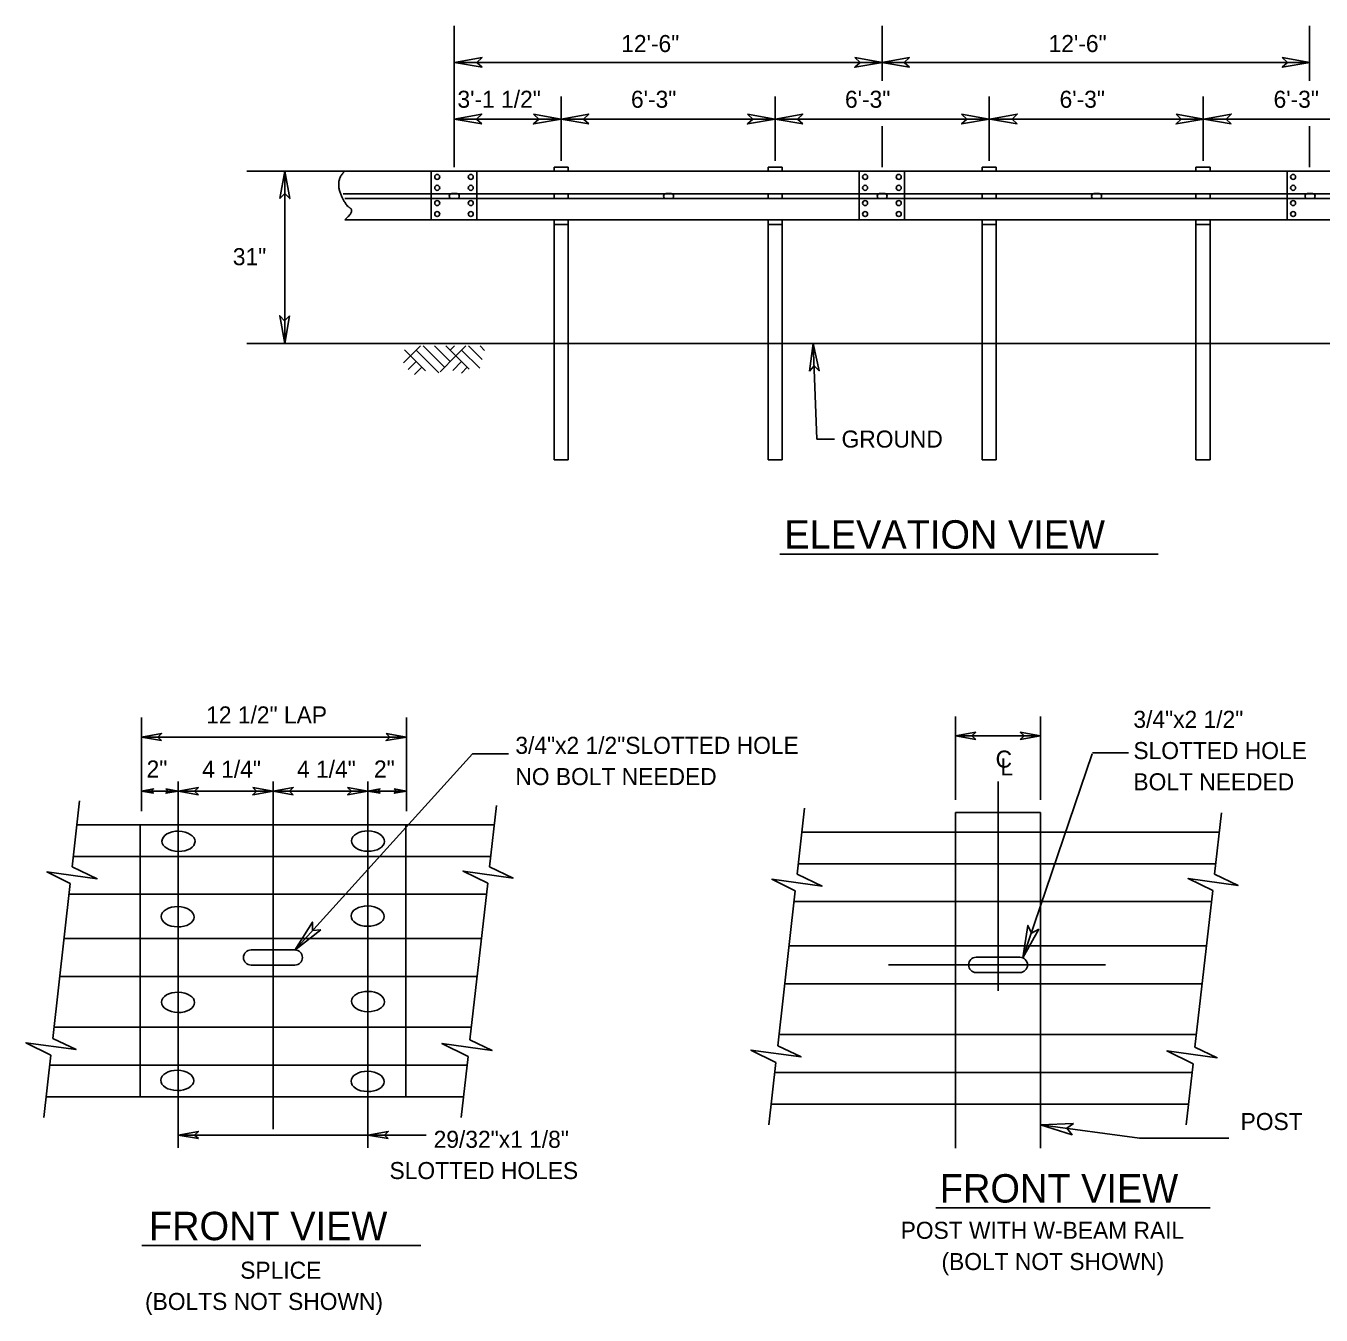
# Model space of a CAD drawing. Extents: x 12.4 to 19.6, y 6 to 16.1.
# Drawn here: x 12.43 to 16.991, y 11.52 to 16.059 of the extents above; entities that cross this region are included whole.
import ezdxf

# ---------------------------------------------------------------- set-up
doc = ezdxf.new("R2010")
doc.units = 0
for name, color, linetype in [('DETL-DIMS', 7, 'Continuous'), ('DETL-LINE', 7, 'Continuous'), ('DETL-NOTE', 7, 'Continuous'), ('DETL-PATT', 7, 'Continuous'), ('DETL-TITL', 7, 'Continuous')]:
    doc.layers.add(name, color=color, linetype=linetype)

msp = doc.modelspace()

# ---------------------------------------------------------------- linework, layer by layer
at = {"layer": 'DETL-DIMS'}
for p, q in [((13.9381, 15.5612), (13.9381, 16.0592)), ((15.4453, 15.8654), (15.4453, 16.0592)), ((16.9503, 15.8654), (16.9503, 16.0592)), ((13.9389, 15.9307), (14.0362, 15.9479)), ((15.4461, 15.9307), (13.9389, 15.9307)), ((13.9389, 15.9307), (14.0362, 15.9136)), ((14.0178, 15.9307), (14.0362, 15.9479)), ((14.0362, 15.9136), (14.0178, 15.9307)), ((15.4461, 15.9307), (15.3489, 15.9479)), ((15.3489, 15.9479), (15.3673, 15.9307)), ((15.4461, 15.9307), (15.3489, 15.9136)), ((15.3673, 15.9307), (15.3489, 15.9136)), ((15.444, 15.9307), (15.5412, 15.9479)), ((15.444, 15.9307), (15.5412, 15.9136)), ((16.9512, 15.9307), (15.444, 15.9307)), ((15.5229, 15.9307), (15.5412, 15.9479)), ((15.5412, 15.9136), (15.5229, 15.9307)), ((16.9512, 15.9307), (16.854, 15.9479)), ((16.854, 15.9479), (16.8723, 15.9307)), ((16.9512, 15.9307), (16.854, 15.9136)), ((16.8723, 15.9307), (16.854, 15.9136)), ((14.3149, 15.5844), (14.3149, 15.8102)), ((15.0685, 15.5844), (15.0685, 15.8102)), ((15.822, 15.5844), (15.822, 15.8102)), ((16.5756, 15.5844), (16.5756, 15.8102)), ((13.9377, 15.7313), (14.035, 15.7484)), ((14.0166, 15.7313), (14.035, 15.7484)), ((14.3145, 15.7313), (14.2173, 15.7484)), ((14.2173, 15.7484), (14.2357, 15.7313)), ((14.3145, 15.7313), (14.4118, 15.7484)), ((14.3934, 15.7313), (14.4118, 15.7484)), ((15.0682, 15.7313), (14.9709, 15.7484)), ((14.9709, 15.7484), (14.9893, 15.7313)), ((15.0683, 15.7313), (15.1655, 15.7484)), ((15.1472, 15.7313), (15.1655, 15.7484)), ((15.8219, 15.7313), (15.7247, 15.7484)), ((15.7247, 15.7484), (15.743, 15.7313)), ((15.824, 15.7313), (15.9212, 15.7484)), ((15.9029, 15.7313), (15.9212, 15.7484)), ((16.5776, 15.7313), (16.4804, 15.7484)), ((16.4804, 15.7484), (16.4987, 15.7313)), ((16.5776, 15.7313), (16.6748, 15.7484)), ((16.6565, 15.7313), (16.6748, 15.7484)), ((13.9377, 15.7313), (14.035, 15.7141)), ((14.3145, 15.7313), (13.9377, 15.7313)), ((14.035, 15.7141), (14.0166, 15.7313)), ((14.3145, 15.7313), (14.2173, 15.7141)), ((14.2357, 15.7313), (14.2173, 15.7141)), ((14.3145, 15.7313), (14.4118, 15.7141)), ((15.0682, 15.7313), (14.3145, 15.7313)), ((14.4118, 15.7141), (14.3934, 15.7313)), ((15.0682, 15.7313), (14.9709, 15.7141)), ((14.9893, 15.7313), (14.9709, 15.7141)), ((15.8219, 15.7313), (15.0683, 15.7313)), ((15.0683, 15.7313), (15.1655, 15.7141)), ((15.1655, 15.7141), (15.1472, 15.7313)), ((15.4453, 15.5612), (15.4453, 15.7056)), ((15.8219, 15.7313), (15.7247, 15.7141)), ((15.743, 15.7313), (15.7247, 15.7141)), ((16.5776, 15.7313), (15.824, 15.7313)), ((15.824, 15.7313), (15.9212, 15.7141)), ((15.9212, 15.7141), (15.9029, 15.7313)), ((16.5776, 15.7313), (16.4804, 15.7141)), ((16.4987, 15.7313), (16.4804, 15.7141)), ((17.3312, 15.7313), (16.5776, 15.7313)), ((16.5776, 15.7313), (16.6748, 15.7141)), ((16.6748, 15.7141), (16.6565, 15.7313)), ((16.9503, 15.5612), (16.9503, 15.7056)), ((13.5526, 15.5482), (13.2075, 15.5482)), ((13.3413, 15.5482), (13.3245, 15.451)), ((13.3413, 15.5482), (13.3413, 14.9412)), ((13.3413, 15.5482), (13.3588, 15.4511)), ((13.8575, 15.376), (13.8575, 15.5482)), ((14.0173, 15.376), (14.0173, 15.5482)), ((15.3646, 15.376), (15.3646, 15.5482)), ((15.5244, 15.376), (15.5244, 15.5482)), ((16.8717, 15.376), (16.8717, 15.5482)), ((13.3245, 15.451), (13.3416, 15.4694)), ((13.3416, 15.4694), (13.3588, 15.4511)), ((13.3413, 14.9412), (13.3239, 15.0384)), ((13.341, 15.0201), (13.3239, 15.0384)), ((13.3581, 15.0385), (13.341, 15.0201)), ((13.3413, 14.9412), (13.3581, 15.0385)), ((13.546, 14.9412), (13.2075, 14.9412)), ((15.2028, 14.9412), (15.1891, 14.8435)), ((15.2149, 14.6036), (15.2028, 14.9412)), ((15.2028, 14.9412), (15.2234, 14.8447)), ((15.1891, 14.8435), (15.2056, 14.8624)), ((15.2056, 14.8624), (15.2234, 14.8447)), ((15.2778, 14.6036), (15.2149, 14.6036)), ((12.8363, 13.2943), (12.8363, 13.6236)), ((13.7697, 13.2943), (13.7697, 13.6236)), ((15.7032, 13.3343), (15.7032, 13.6278)), ((16.0032, 13.3343), (16.0032, 13.6278)), ((16.0032, 13.3343), (16.0032, 13.6278)), ((12.8363, 13.555), (12.9078, 13.5676)), ((12.8363, 13.555), (13.7697, 13.555)), ((12.8363, 13.555), (12.9078, 13.5424)), ((12.8943, 13.555), (12.9078, 13.5676)), ((12.9078, 13.5424), (12.8943, 13.555)), ((13.7697, 13.555), (13.6982, 13.5676)), ((13.6982, 13.5676), (13.7117, 13.555)), ((13.7697, 13.555), (13.6982, 13.5424)), ((13.7117, 13.555), (13.6982, 13.5424)), ((15.7032, 13.5593), (15.7747, 13.5719)), ((15.7032, 13.5593), (16.0032, 13.5593)), ((15.7032, 13.5593), (15.7747, 13.5467)), ((16.0032, 13.5593), (15.7032, 13.5593)), ((15.7612, 13.5593), (15.7747, 13.5719)), ((15.7747, 13.5467), (15.7612, 13.5593)), ((16.0032, 13.5593), (15.9317, 13.5719)), ((15.9452, 13.5593), (15.9317, 13.5719)), ((16.0032, 13.5593), (15.9317, 13.5467)), ((15.9317, 13.5467), (15.9452, 13.5593)), ((13.3772, 12.8052), (14.0028, 13.4955)), ((14.0028, 13.4955), (14.1294, 13.4955)), ((15.9411, 12.7771), (16.1853, 13.4963)), ((16.1864, 13.4998), (16.313, 13.4998)), ((12.8363, 13.3646), (12.8792, 13.3722)), ((12.8363, 13.3646), (12.9659, 13.3646)), ((12.8363, 13.3646), (12.8792, 13.357)), ((12.8711, 13.3646), (12.8792, 13.3722)), ((12.8792, 13.357), (12.8711, 13.3646)), ((12.9659, 13.3646), (12.923, 13.3722)), ((12.923, 13.3722), (12.9311, 13.3646)), ((12.9659, 13.3646), (12.923, 13.357)), ((12.9311, 13.3646), (12.923, 13.357)), ((12.9659, 12.1086), (12.9659, 13.3982)), ((12.9659, 13.3646), (13.0374, 13.3772)), ((12.9659, 13.3646), (13.6341, 13.3646)), ((12.9659, 13.3646), (13.0374, 13.352)), ((13.0239, 13.3646), (13.0374, 13.3772)), ((13.0374, 13.352), (13.0239, 13.3646)), ((13.3, 13.3646), (13.2285, 13.3772)), ((13.2285, 13.3772), (13.242, 13.3646)), ((13.3, 13.3646), (13.2285, 13.352)), ((13.242, 13.3646), (13.2285, 13.352)), ((13.3, 12.174), (13.3, 13.3982)), ((13.3, 13.3646), (13.3715, 13.3772)), ((13.3, 13.3646), (13.3715, 13.352)), ((13.358, 13.3646), (13.3715, 13.3772)), ((13.3715, 13.352), (13.358, 13.3646)), ((13.6341, 13.3646), (13.5626, 13.3772)), ((13.5626, 13.3772), (13.5761, 13.3646)), ((13.6341, 13.3646), (13.5626, 13.352)), ((13.5761, 13.3646), (13.5626, 13.352)), ((13.6341, 12.1086), (13.6341, 13.3982)), ((13.6341, 13.3646), (13.677, 13.3722)), ((13.6341, 13.3646), (13.7697, 13.3646)), ((13.6341, 13.3646), (13.677, 13.357)), ((13.6689, 13.3646), (13.677, 13.3722)), ((13.677, 13.357), (13.6689, 13.3646)), ((13.7697, 13.3646), (13.7268, 13.3722)), ((13.7268, 13.3722), (13.7349, 13.3646)), ((13.7697, 13.3646), (13.7268, 13.357)), ((13.7349, 13.3646), (13.7268, 13.357)), ((15.8532, 13.3984), (15.8532, 12.6612)), ((13.3772, 12.8052), (13.4388, 12.9036)), ((13.3772, 12.8052), (13.4687, 12.8766)), ((13.4393, 12.8741), (13.4388, 12.9036)), ((13.4687, 12.8766), (13.4393, 12.8741)), ((15.9411, 12.7771), (15.9588, 12.8919)), ((15.9411, 12.7771), (15.997, 12.8789)), ((15.971, 12.865), (15.9588, 12.8919)), ((15.997, 12.8789), (15.971, 12.865)), ((16.2323, 12.7527), (15.4681, 12.7527)), ((16.0032, 12.19), (16.1193, 12.1946)), ((16.0032, 12.19), (16.3517, 12.1424)), ((16.0032, 12.19), (16.1139, 12.1547)), ((16.1193, 12.1946), (16.0952, 12.1774)), ((12.9659, 12.1535), (13.0374, 12.1661)), ((12.9659, 12.1535), (13.0374, 12.1409)), ((12.9659, 12.1535), (13.6341, 12.1535)), ((13.0239, 12.1535), (13.0374, 12.1661)), ((13.0374, 12.1409), (13.0239, 12.1535)), ((13.6341, 12.1535), (13.7056, 12.1661)), ((13.6341, 12.1535), (13.839, 12.1535)), ((13.6341, 12.1535), (13.7056, 12.1409)), ((13.6921, 12.1535), (13.7056, 12.1661)), ((13.7056, 12.1409), (13.6921, 12.1535)), ((16.0952, 12.1774), (16.1139, 12.1547)), ((16.3517, 12.1424), (16.6666, 12.1424))]:
    msp.add_line(p, q, dxfattribs=at)
for points in [[(14.0362, 15.9136), (13.9389, 15.9307), (14.0362, 15.9479), (14.0178, 15.9307)], [(15.3489, 15.9479), (15.4461, 15.9307), (15.3489, 15.9136), (15.3673, 15.9307)], [(15.5412, 15.9136), (15.444, 15.9307), (15.5412, 15.9479), (15.5229, 15.9307)], [(16.854, 15.9479), (16.9512, 15.9307), (16.854, 15.9136), (16.8723, 15.9307)], [(14.035, 15.7141), (13.9377, 15.7313), (14.035, 15.7484), (14.0166, 15.7313)], [(14.2173, 15.7484), (14.3145, 15.7313), (14.2173, 15.7141), (14.2357, 15.7313)], [(14.4118, 15.7141), (14.3145, 15.7313), (14.4118, 15.7484), (14.3934, 15.7313)], [(14.9709, 15.7484), (15.0682, 15.7313), (14.9709, 15.7141), (14.9893, 15.7313)], [(15.1655, 15.7141), (15.0683, 15.7313), (15.1655, 15.7484), (15.1472, 15.7313)], [(15.7247, 15.7484), (15.8219, 15.7313), (15.7247, 15.7141), (15.743, 15.7313)], [(15.9212, 15.7141), (15.824, 15.7313), (15.9212, 15.7484), (15.9029, 15.7313)], [(16.4804, 15.7484), (16.5776, 15.7313), (16.4804, 15.7141), (16.4987, 15.7313)], [(16.6748, 15.7141), (16.5776, 15.7313), (16.6748, 15.7484), (16.6565, 15.7313)], [(13.3245, 15.451), (13.3413, 15.5482), (13.3588, 15.4511), (13.3416, 15.4694)], [(13.3581, 15.0385), (13.3413, 14.9412), (13.3239, 15.0384), (13.341, 15.0201)], [(15.1891, 14.8435), (15.2028, 14.9412), (15.2234, 14.8447), (15.2056, 14.8624)], [(12.9078, 13.5424), (12.8363, 13.555), (12.9078, 13.5676), (12.8943, 13.555)], [(13.6982, 13.5676), (13.7697, 13.555), (13.6982, 13.5424), (13.7117, 13.555)], [(15.7747, 13.5467), (15.7032, 13.5593), (15.7747, 13.5719), (15.7612, 13.5593)], [(15.9317, 13.5467), (16.0032, 13.5593), (15.9317, 13.5719), (15.9452, 13.5593)], [(12.8792, 13.357), (12.8363, 13.3646), (12.8792, 13.3722), (12.8711, 13.3646)], [(12.923, 13.3722), (12.9659, 13.3646), (12.923, 13.357), (12.9311, 13.3646)], [(13.0374, 13.352), (12.9659, 13.3646), (13.0374, 13.3772), (13.0239, 13.3646)], [(13.2285, 13.3772), (13.3, 13.3646), (13.2285, 13.352), (13.242, 13.3646)], [(13.3715, 13.352), (13.3, 13.3646), (13.3715, 13.3772), (13.358, 13.3646)], [(13.5626, 13.3772), (13.6341, 13.3646), (13.5626, 13.352), (13.5761, 13.3646)], [(13.677, 13.357), (13.6341, 13.3646), (13.677, 13.3722), (13.6689, 13.3646)], [(13.7268, 13.3722), (13.7697, 13.3646), (13.7268, 13.357), (13.7349, 13.3646)], [(13.4687, 12.8766), (13.3772, 12.8052), (13.4388, 12.9036), (13.4393, 12.8741)], [(15.997, 12.8789), (15.9411, 12.7771), (15.9588, 12.8919), (15.971, 12.865)], [(16.1193, 12.1946), (16.0032, 12.19), (16.1139, 12.1547), (16.0952, 12.1774)], [(13.0374, 12.1409), (12.9659, 12.1535), (13.0374, 12.1661), (13.0239, 12.1535)], [(13.7056, 12.1409), (13.6341, 12.1535), (13.7056, 12.1661), (13.6921, 12.1535)]]:
    msp.add_lwpolyline(points, close=True, dxfattribs=at)
at = {"layer": 'DETL-LINE'}
for p, q in [((14.29, 15.5612), (14.3399, 15.5612)), ((14.29, 15.5482), (14.29, 15.5612)), ((14.3399, 15.5612), (14.3399, 15.5482)), ((15.0432, 15.5612), (15.0931, 15.5612)), ((15.0432, 15.5482), (15.0432, 15.5612)), ((15.0931, 15.5612), (15.0931, 15.5482)), ((15.7971, 15.5612), (15.847, 15.5612)), ((15.7971, 15.5482), (15.7971, 15.5612)), ((15.847, 15.5612), (15.847, 15.5482)), ((16.5503, 15.5612), (16.6002, 15.5612)), ((16.5503, 15.5482), (16.5503, 15.5612)), ((16.6002, 15.5612), (16.6002, 15.5482)), ((13.5526, 15.5482), (18.6517, 15.5482)), ((13.5475, 15.4682), (18.6567, 15.4682)), ((13.9293, 15.4688), (13.9469, 15.4688)), ((14.29, 15.4518), (14.29, 15.4682)), ((14.3399, 15.4518), (14.3399, 15.4682)), ((14.6842, 15.4688), (14.7019, 15.4688)), ((15.0432, 15.4518), (15.0432, 15.4682)), ((15.0931, 15.4518), (15.0931, 15.4682)), ((15.4364, 15.4688), (15.4541, 15.4688)), ((15.7971, 15.4518), (15.7971, 15.4682)), ((15.847, 15.4518), (15.847, 15.4682)), ((16.1914, 15.4688), (16.209, 15.4688)), ((16.5503, 15.4518), (16.5503, 15.4682)), ((16.6002, 15.4518), (16.6002, 15.4682)), ((16.9436, 15.4688), (16.9612, 15.4688)), ((13.5528, 15.4518), (18.6515, 15.4518)), ((13.9293, 15.4511), (13.9469, 15.4511)), ((14.6842, 15.4511), (14.7019, 15.4511)), ((15.4364, 15.4511), (15.4541, 15.4511)), ((16.1914, 15.4511), (16.209, 15.4511)), ((16.9436, 15.4511), (16.9612, 15.4511)), ((13.5526, 15.376), (18.6516, 15.376)), ((14.29, 15.376), (14.29, 14.9412)), ((14.29, 15.3726), (14.29, 15.3596)), ((14.3399, 15.376), (14.3399, 14.9412)), ((14.3399, 15.3596), (14.3399, 15.3726)), ((15.0432, 15.376), (15.0432, 14.9412)), ((15.0432, 15.3726), (15.0432, 15.3596)), ((15.0931, 15.376), (15.0931, 14.9412)), ((15.0931, 15.3596), (15.0931, 15.3726)), ((15.7971, 15.376), (15.7971, 14.9412)), ((15.7971, 15.3726), (15.7971, 15.3596)), ((15.847, 15.376), (15.847, 14.9412)), ((15.847, 15.3596), (15.847, 15.3726)), ((16.5503, 15.376), (16.5503, 14.9412)), ((16.5503, 15.3726), (16.5503, 15.3596)), ((16.6002, 15.376), (16.6002, 14.9412)), ((16.6002, 15.3596), (16.6002, 15.3726)), ((14.29, 15.3596), (14.3399, 15.3596)), ((15.0432, 15.3596), (15.0931, 15.3596)), ((15.7971, 15.3596), (15.847, 15.3596)), ((16.5503, 15.3596), (16.6002, 15.3596)), ((13.546, 14.9412), (18.213, 14.9412)), ((14.29, 14.5311), (14.29, 14.9412)), ((14.3399, 14.5311), (14.3399, 14.9412)), ((15.0432, 14.5311), (15.0432, 14.9412)), ((15.0931, 14.5311), (15.0931, 14.9412)), ((15.7971, 14.5311), (15.7971, 14.9412)), ((15.847, 14.5311), (15.847, 14.9412)), ((16.5503, 14.5311), (16.5503, 14.9412)), ((16.6002, 14.5311), (16.6002, 14.9412)), ((14.3399, 14.5311), (14.29, 14.5311)), ((15.0931, 14.5311), (15.0432, 14.5311)), ((15.847, 14.5311), (15.7971, 14.5311)), ((16.6002, 14.5311), (16.5503, 14.5311)), ((12.6191, 13.3304), (12.5927, 13.0979)), ((14.0872, 13.3146), (14.0627, 13.0982)), ((15.1723, 13.3045), (15.1459, 13.072)), ((15.7032, 13.2889), (15.7032, 13.2204)), ((15.7032, 13.2889), (16.0032, 13.2889)), ((16.0032, 13.2889), (16.0032, 13.2204)), ((16.6404, 13.2887), (16.6159, 13.0723)), ((12.6095, 13.2463), (14.0795, 13.2463)), ((12.8323, 12.2886), (12.8323, 13.2463)), ((13.7677, 12.2886), (13.7677, 13.2463)), ((15.1627, 13.2204), (16.6327, 13.2204)), ((15.7032, 13.2204), (15.7032, 12.1071)), ((16.0032, 13.2204), (16.0032, 12.1071)), ((12.5969, 13.1349), (14.0669, 13.1349)), ((15.1501, 13.109), (16.6201, 13.109)), ((12.5861, 13.0399), (12.5242, 12.4935)), ((12.5818, 13.0013), (14.0517, 13.0013)), ((14.0561, 13.0402), (13.9936, 12.4888)), ((15.1393, 13.014), (15.0774, 12.4676)), ((16.6093, 13.0143), (16.5468, 12.4629)), ((15.135, 12.9754), (16.6049, 12.9754)), ((12.5641, 12.8454), (14.034, 12.8454)), ((15.1173, 12.8195), (16.5872, 12.8195)), ((13.2643, 12.8053), (13.2228, 12.8053)), ((13.2643, 12.8053), (13.3371, 12.8053)), ((13.3772, 12.8053), (13.3371, 12.8053)), ((15.8175, 12.7794), (15.776, 12.7794)), ((15.8175, 12.7794), (15.8903, 12.7794)), ((15.9304, 12.7794), (15.8903, 12.7794)), ((13.2659, 12.7519), (13.2228, 12.7519)), ((13.2659, 12.7519), (13.3355, 12.7519)), ((13.3772, 12.7519), (13.3355, 12.7519)), ((15.8191, 12.726), (15.776, 12.726)), ((15.8191, 12.726), (15.8887, 12.726)), ((15.9304, 12.726), (15.8887, 12.726)), ((12.5489, 12.7118), (14.0189, 12.7118)), ((15.1021, 12.6859), (16.5721, 12.6859)), ((12.5287, 12.5336), (13.9987, 12.5336)), ((15.0819, 12.5077), (16.5519, 12.5077)), ((12.5176, 12.4354), (12.4926, 12.2151)), ((13.987, 12.4306), (13.9626, 12.2151)), ((15.0708, 12.4095), (15.0458, 12.1892)), ((12.5136, 12.4), (13.9835, 12.4)), ((15.0668, 12.3741), (16.5367, 12.3741)), ((16.5402, 12.4047), (16.5158, 12.1892)), ((12.501, 12.2886), (13.9709, 12.2886)), ((15.0542, 12.2627), (16.5241, 12.2627))]:
    msp.add_line(p, q, dxfattribs=at)
for points in [[(12.5861, 13.0399), (12.504, 13.0801), (12.6806, 13.0561), (12.5927, 13.0979)], [(14.0561, 13.0402), (13.9691, 13.0828), (14.1457, 13.0587), (14.0627, 13.0982)], [(15.1393, 13.014), (15.0572, 13.0542), (15.2338, 13.0302), (15.1459, 13.072)], [(16.6093, 13.0143), (16.5223, 13.0569), (16.6989, 13.0328), (16.6159, 13.0723)], [(12.5176, 12.4354), (12.4298, 12.4784), (12.6064, 12.4544), (12.5242, 12.4935)], [(13.987, 12.4306), (13.8949, 12.4757), (14.0715, 12.4517), (13.9936, 12.4888)], [(15.0708, 12.4095), (14.983, 12.4525), (15.1596, 12.4285), (15.0774, 12.4676)], [(16.5402, 12.4047), (16.4481, 12.4498), (16.6247, 12.4258), (16.5468, 12.4629)]]:
    msp.add_lwpolyline(points, dxfattribs=at)
for centre in [(13.8782, 15.5274), (13.9965, 15.5274), (15.3853, 15.5274), (15.5037, 15.5274), (16.8925, 15.5274), (13.8782, 15.489), (13.9965, 15.489), (15.3853, 15.489), (15.5037, 15.489), (16.8925, 15.489), (13.8782, 15.4352), (13.9965, 15.4352), (15.3853, 15.4352), (15.5037, 15.4352), (16.8925, 15.4352), (13.8782, 15.3968), (13.9965, 15.3968), (15.3853, 15.3968), (15.5037, 15.3968), (16.8925, 15.3968)]:
    msp.add_circle(centre, 0.00883, dxfattribs=at)
for centre, radius, start, end in [((13.9293, 15.46), 0.00883, 90, 270), ((13.9469, 15.46), 0.00883, 270, 90), ((14.6842, 15.46), 0.00883, 90, 270), ((14.7019, 15.46), 0.00883, 270, 90), ((15.4364, 15.46), 0.00883, 90, 270), ((15.4541, 15.46), 0.00883, 270, 90), ((16.1914, 15.46), 0.00883, 90, 270), ((16.209, 15.46), 0.00883, 270, 90), ((16.9436, 15.46), 0.00883, 90, 270), ((16.9612, 15.46), 0.00883, 270, 90), ((13.2228, 12.7786), 0.0267, 90, 270), ((13.3771, 12.7786), 0.0267, 270, 90), ((15.7761, 12.7527), 0.0267, 90, 270), ((15.9304, 12.7527), 0.0267, 270, 90)]:
    msp.add_arc(centre, radius, start, end, dxfattribs=at)
for centre in [(12.9672, 13.1879), (13.6344, 13.1886), (12.9643, 12.9222), (13.633, 12.9244), (12.9657, 12.6209), (13.6344, 12.6238), (12.9629, 12.346), (13.633, 12.3424)]:
    msp.add_ellipse(centre, major_axis=(-0.0582, 0.001), ratio=0.614151, dxfattribs=at)
msp.add_open_spline([(13.5526, 15.376), (13.5888, 15.4071), (13.5518, 15.4303), (13.5208, 15.5165), (13.5526, 15.5482)], degree=2, dxfattribs=at)
at = {"layer": 'DETL-PATT'}
for p, q in [((13.7841, 14.897), (13.7629, 14.9182)), ((13.7841, 14.897), (13.8193, 14.9323)), ((13.8841, 14.837), (13.8041, 14.917)), ((13.9043, 14.8571), (13.8288, 14.9323)), ((13.9242, 14.877), (13.8689, 14.9323)), ((13.9441, 14.897), (13.9089, 14.9323)), ((13.9242, 14.917), (13.9395, 14.9323)), ((13.9441, 14.897), (13.9795, 14.9323)), ((14.0278, 14.8536), (13.9642, 14.917)), ((14.0366, 14.8848), (13.989, 14.9323)), ((14.0453, 14.916), (14.0291, 14.9323)), ((13.7593, 14.8723), (13.7841, 14.897)), ((13.776, 14.8489), (13.8041, 14.877)), ((13.837, 14.8442), (13.7841, 14.897)), ((13.8888, 14.8416), (13.9441, 14.897)), ((13.9333, 14.8461), (13.9642, 14.877)), ((13.9912, 14.85), (13.9441, 14.897)), ((13.7982, 14.8311), (13.8241, 14.8571)), ((13.9638, 14.8366), (13.9843, 14.8571))]:
    msp.add_line(p, q, dxfattribs=at)
at = {"layer": 'DETL-TITL'}
for p, q in [((15.0854, 14.1996), (16.4169, 14.1996)), ((15.6345, 11.897), (16.6005, 11.897)), ((12.8378, 11.7645), (13.8204, 11.7645))]:
    msp.add_line(p, q, dxfattribs=at)

# ---------------------------------------------------------------- texts
at = {"layer": 'DETL-NOTE'}
for s, p in [('12\'-6" ', (14.5264, 15.9671)), ('12\'-6" ', (16.0314, 15.9671)), ('3\'-1 1/2"', (13.9496, 15.7709)), ('6\'-3"', (14.5606, 15.7709)), ('6\'-3"', (15.3143, 15.7709)), ('6\'-3"', (16.07, 15.7709)), ('6\'-3"', (16.8236, 15.7709)), ('31"', (13.1585, 15.2166)), ('GROUND', (15.3022, 14.5743)), ('12 1/2" LAP', (13.0647, 13.603)), ('3/4"x2 1/2" ', (16.33, 13.5875)), ('3/4"x2 1/2"SLOTTED HOLE', (14.1535, 13.4959)), ('C', (15.8446, 13.4474)), ('SLOTTED HOLE ', (16.33, 13.4775)), ('2"', (12.8548, 13.4126)), ('4 1/4" ', (13.0506, 13.4118)), ('4 1/4" ', (13.3845, 13.4118)), ('2"', (13.6556, 13.4126)), ('L', (15.8618, 13.42)), ('NO BOLT NEEDED ', (14.1535, 13.3859)), ('BOLT NEEDED', (16.33, 13.3675)), ('POST', (16.7074, 12.1713)), ('29/32"x1 1/8"', (13.8657, 12.1086)), ('SLOTTED HOLES', (13.7103, 11.9986)), ('POST WITH W-BEAM RAIL', (15.5103, 11.7882)), ('(BOLT NOT SHOWN)', (15.6541, 11.6782)), ('SPLICE', (13.1846, 11.6477)), ('(BOLTS NOT SHOWN)', (12.8493, 11.5377))]:
    msp.add_text(s, height=0.06, dxfattribs=at).set_placement(p)
at = {"layer": 'DETL-TITL'}
for s, p in [('ELEVATION VIEW', (15.1005, 14.2185)), ('FRONT VIEW ', (15.6482, 11.9159)), ('FRONT VIEW ', (12.863, 11.7834))]:
    msp.add_text(s, height=0.1, dxfattribs=at).set_placement(p)

doc.saveas('drawing.dxf')
